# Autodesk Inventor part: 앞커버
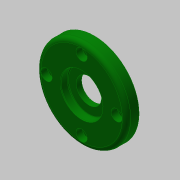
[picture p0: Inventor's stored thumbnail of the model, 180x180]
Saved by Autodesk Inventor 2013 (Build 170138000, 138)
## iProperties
Created: 2019-01
Part Number: 앞커버
Material: 일반
Document SubType Name: Modeling
Designer: mduedu
Density: 1 g/cm^3
Mass: 24.4849 g
Surface Area: 91.8017 cm^2
Volume: 24.4849 cm^3
Author: mduedu
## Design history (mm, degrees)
sketch "스케치1"
  geometry: L1 (0, 0)-(9, 0); L2 (9, 0)-(9, 32); L3 (9, 32)-(0, 32); L4 (0, 32)-(0, 0); L5 (9, 0)-(12, 0); L6 (12, 0)-(12, 20); L7 (12, 20)-(9, 20); L8 (9, 20)-(9, 0)
  constraints: 16 end point, 4 parallel, 2 horizontal, 2 perpendicular
  dimensions: "d0" = 12 distance between parallel lines of L6 L4; "d2" = 64 diameter of L3 L1; "d3" = 40 diameter of L7 L5; "d4" = 3 distance between parallel lines of L6 L2
revolve "회전1" sketch "스케치1" stored, may be unused: angle "d5" = 90 deg
sketch "스케치2"
  geometry: L1 (0, -32)-(0, 32) reference; L2 (0, 32)-(9, 32) reference; L3 (9, 32)-(9, 20) reference; L4 (9, 20)-(12, 20) reference; L5 (12, 20)-(12, -20) reference; L6 (12, -20)-(9, -20) reference; L7 (9, -20)-(9, -32) reference; L8 (9, -32)-(0, -32) reference; L9 (0, 0)-(5.2, 0); L10 (5.2, 0)-(5.2, 15); L11 (5.2, 15)-(0, 15); L12 (0, 15)-(0, 0); L13 (5.2, 0)-(9, 0); L14 (9, 0)-(9, 9); L15 (9, 9)-(5.2, 9); L16 (5.2, 9)-(5.2, 0); L17 (9, 0)-(12, 0); L18 (12, 0)-(12, 15); L19 (12, 15)-(9, 15); L20 (9, 15)-(9, 0)
  constraints: 24 end point, 6 parallel, 3 horizontal, 3 perpendicular, 1 point on line
  dimensions: "d6" = 3 distance of L18.end L19.end; "d8" = 5.2 distance of L10.end L11.end; "d9" = 30 diameter of L11 L9; "d10" = 18 diameter of L15 L13; "d11" = 30 diameter of L19 L17
revolve "회전2" sketch "스케치2" stored, may be unused: angle "d12" = 90 deg
chamfer "모따기1" distance "d13" = 0.5; stored, may be unused: second distance "d14" = 2, angle "d15" = 30 deg
fillet "모깎기1" dims "d16" = 0.5
fillet "모깎기2" dims "d17" = 3
fillet "모깎기3" dims "d18" = 3
chamfer "모따기2" distance "d24" = 1; stored, may be unused: second distance "d25" = 2, angle "d26" = 45 deg
sketch "스케치3" dims "d19" = 50
  geometry: 6 further points
  constraints: 2 vertical alignment, 1 coincident, 7 other
  dimensions: "d22" = 360 deg dimension on point (0, 0) point (0, 25) (derived)
sketch "스케치4"
  geometry: 4 further points
  constraints: 4 other
hole "구멍1" sketch "스케치4" at (-25, 0), (0, -25), (25, 0), (0, 25) diameter "d27" = 4.5; stored, may be unused: countersink angle "d31" = 90 deg, drill point angle "d33" = 0 deg; dims "d28" = 6, "d29" = 8, "d30" = 4.6, "d32" = 8
node "솔리드1"
node "절단 모서리 투영1"
